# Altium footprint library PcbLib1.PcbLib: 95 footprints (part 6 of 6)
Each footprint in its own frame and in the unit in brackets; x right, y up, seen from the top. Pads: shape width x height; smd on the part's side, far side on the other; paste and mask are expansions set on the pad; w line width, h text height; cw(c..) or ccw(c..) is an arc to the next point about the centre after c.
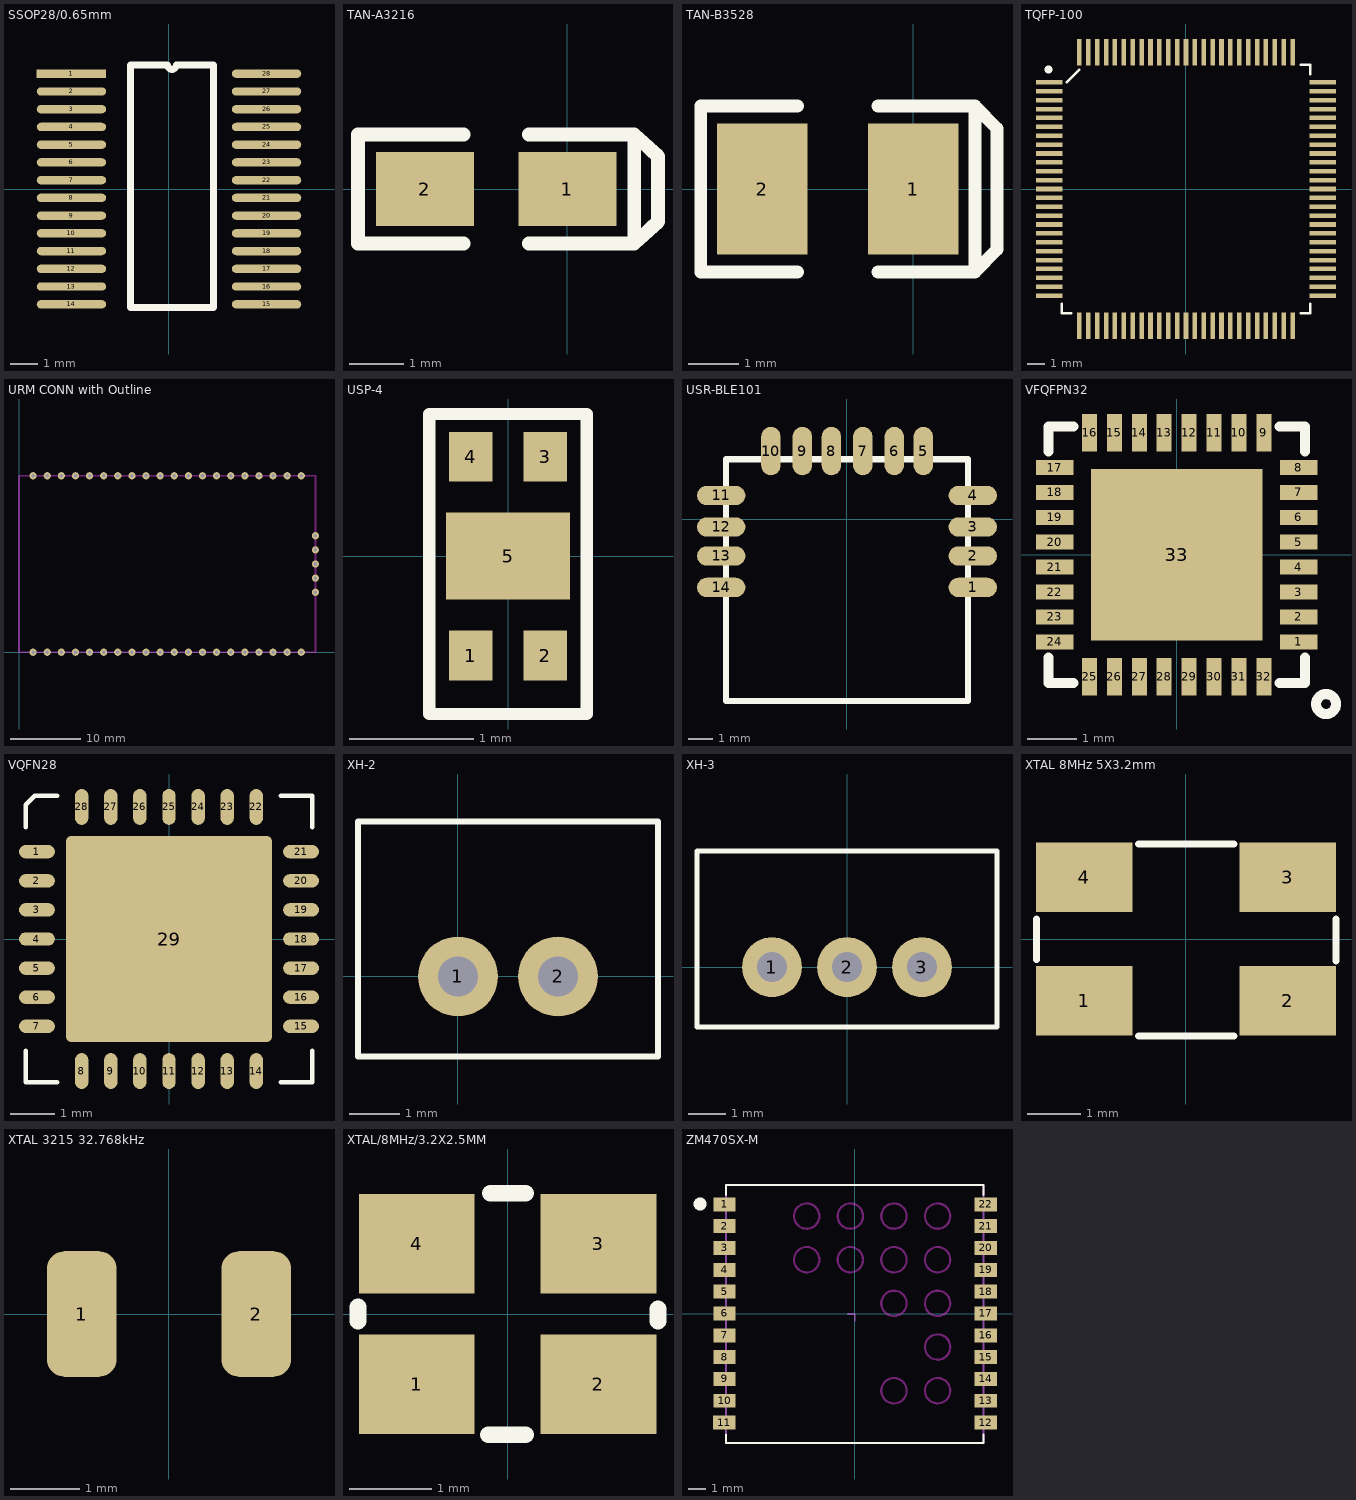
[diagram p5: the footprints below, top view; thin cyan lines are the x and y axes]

## SSOP28/0.65mm [mm]
pads (28):
  rect 2.54x0.305 smd: 1(-3.575,4.225)
  oval 2.54x0.305 smd: 2(-3.575,3.575) 3(-3.575,2.925) 4(-3.575,2.275) 5(-3.575,1.625) 6(-3.575,0.975) 7(-3.575,0.325) 8(-3.575,-0.325) 9(-3.575,-0.975) 10(-3.575,-1.625) 11(-3.575,-2.275) 12(-3.575,-2.925) 13(-3.575,-3.575) 14(-3.575,-4.225) 15(3.575,-4.225) 16(3.575,-3.575) 17(3.575,-2.925) 18(3.575,-2.275) 19(3.575,-1.625) 20(3.575,-0.975) 21(3.575,-0.325) 22(3.575,0.325) 23(3.575,0.975) 24(3.575,1.625) 25(3.575,2.275) 26(3.575,2.925) 27(3.575,3.575) 28(3.575,4.225)
Top Overlay:
  lines w0.254: -1.416,-4.348 -1.416,4.542 -0.051,4.542 ccw(c0.108,4.542) 0.267,4.542 1.632,4.542 1.632,-4.348 -1.416,-4.348
3D body: height 1.9, standoff 0, extent -3.812,-5.1 3.988,5.1

## TAN-A3216 [mm]
pads (2):
  rect 1.8x1.35 smd: 1(0,0) 2(-2.62,0)
Top Overlay:
  lines w0.254: -1.91,-1.002 -3.847,-1.002 -3.847,1.002 -1.91,1.002 ; -0.71,-1.002 1.227,-1.002 ; -0.71,1.002 1.227,1.002 ; 1.227,-1.002 1.663,-0.6 1.663,0.6 1.227,1.002 ; 1.227,-1.002 1.227,1.002
3D body: height 1.71, standoff 0, extent -3.01,-0.84 0.39,0.84

## TAN-B3528 [mm]
pads (2):
  rect 1.8x2.6 smd: 1(0,0) 2(-3,0)
Top Overlay:
  lines w0.254: -2.3,-1.65 -4.227,-1.65 -4.227,1.65 -2.3,1.65 ; -0.7,-1.65 1.227,-1.65 ; -0.7,1.65 1.227,1.65 ; 1.227,-1.65 1.227,1.65 ; 1.227,-1.65 1.663,-1.2 1.663,1.2 1.227,1.65
3D body: height 2.03, standoff 0, extent -3.35,-1.465 0.35,1.465

## TQFP-100 [mm]
pads (100):
  rect 1.5x0.254 smd: 1(-7.7,6) 2(-7.7,5.5) 3(-7.7,5) 4(-7.7,4.5) 5(-7.7,4) 6(-7.7,3.5) 7(-7.7,3) 8(-7.7,2.5) 9(-7.7,2) 10(-7.7,1.5) 11(-7.7,1) 12(-7.7,0.5) 13(-7.7,0) 14(-7.7,-0.5) 15(-7.7,-1) 16(-7.7,-1.5) 17(-7.7,-2) 18(-7.7,-2.5) 19(-7.7,-3) 20(-7.7,-3.5) 21(-7.7,-4) 22(-7.7,-4.5) 23(-7.7,-5) 24(-7.7,-5.5) 25(-7.7,-6) 51(7.7,-6) 52(7.7,-5.5) 53(7.7,-5) 54(7.7,-4.5) 55(7.7,-4) 56(7.7,-3.5) 57(7.7,-3) 58(7.7,-2.5) 59(7.7,-2) 60(7.7,-1.5) 61(7.7,-1) 62(7.7,-0.5) 63(7.7,0) 64(7.7,0.5) 65(7.7,1) 66(7.7,1.5) 67(7.7,2) 68(7.7,2.5) 69(7.7,3) 70(7.7,3.5) 71(7.7,4) 72(7.7,4.5) 73(7.7,5) 74(7.7,5.5) 75(7.7,6)
  rect 0.254x1.5 smd: 26(-6,-7.7) 27(-5.5,-7.7) 28(-5,-7.7) 29(-4.5,-7.7) 30(-4,-7.7) 31(-3.5,-7.7) 32(-3,-7.7) 33(-2.5,-7.7) 34(-2,-7.7) 35(-1.5,-7.7) 36(-1,-7.7) 37(-0.5,-7.7) 38(0,-7.7) 39(0.5,-7.7) 40(1,-7.7) 41(1.5,-7.7) 42(2,-7.7) 43(2.5,-7.7) 44(3,-7.7) 45(3.5,-7.7) 46(4,-7.7) 47(4.5,-7.7) 48(5,-7.7) 49(5.5,-7.7) 50(6,-7.7) 76(6,7.7) 77(5.5,7.7) 78(5,7.7) 79(4.5,7.7) 80(4,7.7) 81(3.5,7.7) 82(3,7.7) 83(2.5,7.7) 84(2,7.7) 85(1.5,7.7) 86(1,7.7) 87(0.5,7.7) 88(0,7.7) 89(-0.5,7.7) 90(-1,7.7) 91(-1.5,7.7) 92(-2,7.7) 93(-2.5,7.7) 94(-3,7.7) 95(-3.5,7.7) 96(-4,7.7) 97(-4.5,7.7) 98(-5,7.7) 99(-5.5,7.7) 100(-6,7.7)
Top Overlay:
  circle w0.254: c-7.747,6.731 r0.1
  lines w0.152: -7,-6.457 -7,-7 -6.457,-7 ; -6.712,6.018 -6.018,6.712 ; 6.457,-7 7,-7 7,-6.457 ; 6.457,7 7,7 7,6.457

## URM CONN with Outline [mil]
pads (45):
  round 40 hole 20 mask+2.5: 1(1574.8,983.13) 2(1496.06,983.13) 3(1417.32,983.13) 4(1338.58,983.13) 5(1259.84,983.13) 6(1181.1,983.13) 7(1102.36,983.13) 8(1023.62,983.13) 9(944.88,983.13) 10(866.14,983.13) 11(787.4,983.13) 12(708.66,983.13) 13(629.92,983.13) 14(551.18,983.13) 15(472.44,983.13) 16(393.7,983.13) 17(314.96,983.13) 18(236.22,983.13) 19(157.48,983.13) 20(78.74,983.13) 21(78.74,-1.13) 22(157.48,-1.13) 23(236.22,-1.13) 24(314.96,-1.13) 25(393.7,-1.13) 26(472.44,-1.13) 27(551.18,-1.13) 28(629.92,-1.13) 29(708.66,-1.13) 30(787.4,-1.13) 31(866.14,-1.13) 32(944.88,-1.13) 33(1023.62,-1.13) 34(1102.36,-1.13) 35(1181.1,-1.13) 36(1259.84,-1.13) 37(1338.58,-1.13) 38(1417.32,-1.13) 39(1496.06,-1.13) 40(1574.8,-1.13) G1(1653.54,648.48) G2(1653.54,491) G3(1653.54,333.52) NC(1653.54,412.26) TX(1653.54,569.74)
Keep-Out Layer:
  lines w10: 0,-1.13 1653.54,-1.13 1653.54,983.13 0,983.13 0,-1.13

## USP-4 [mm]
pads (5):
  rect 0.35x0.4 smd paste+0 mask+0.04: 1(-0.3,-0.8) 2(0.3,-0.8) 3(0.3,0.8) 4(-0.3,0.8)
  rect 1x0.7 smd paste+0 mask+0.04: 5(0,0)
Top Overlay:
  lines w0.1: -0.635,-1.27 -0.635,1.143 0.635,1.143 0.635,-1.27 -0.635,-1.27

## USR-BLE101 [mm]
pads (14):
  oval 2x0.8 smd: 1(5.2,-2.818) 2(5.2,-1.518) 3(5.2,-0.318) 4(5.2,0.982) 11(-5.2,0.982) 12(-5.2,-0.318) 13(-5.2,-1.518) 14(-5.2,-2.818)
  oval 0.8x2 smd: 5(3.154,2.818) 6(1.954,2.818) 7(0.654,2.818) 8(-0.646,2.818) 9(-1.846,2.818) 10(-3.146,2.818)
Top Overlay:
  lines w0.254: -5,-7.518 5,-7.518 5,2.482 -5,2.482 -5,-7.518

## VFQFPN32 [mm] "CR95HF"
pads (33):
  rect 0.75x0.3 smd paste+0 mask+0.04: 1(2.45,-1.75) 2(2.45,-1.25) 3(2.45,-0.75) 4(2.45,-0.25) 5(2.45,0.25) 6(2.45,0.75) 7(2.45,1.25) 8(2.45,1.75) 17(-2.45,1.75) 18(-2.45,1.25) 19(-2.45,0.75) 20(-2.45,0.25) 21(-2.45,-0.25) 22(-2.45,-0.75) 23(-2.45,-1.25) 24(-2.45,-1.75)
  rect 0.3x0.75 smd paste+0 mask+0.04: 9(1.75,2.45) 10(1.25,2.45) 11(0.75,2.45) 12(0.25,2.45) 13(-0.25,2.45) 14(-0.75,2.45) 15(-1.25,2.45) 16(-1.75,2.45) 25(-1.75,-2.45) 26(-1.25,-2.45) 27(-0.75,-2.45) 28(-0.25,-2.45) 29(0.25,-2.45) 30(0.75,-2.45) 31(1.25,-2.45) 32(1.75,-2.45)
  rect 3.45x3.45 smd paste-0.025 mask+0.1: 33(0,0)
Top Overlay:
  lines w0.2: -2.575,-2.069 -2.575,-2.575 -2.069,-2.575 ; -2.575,2.069 -2.575,2.575 -2.069,2.575 ; 2.069,-2.575 2.575,-2.575 2.575,-2.069 ; 2.069,2.575 2.575,2.575 2.575,2.069 ; 2.8,-3.007 2.801,-3.021 2.803,-3.035 2.806,-3.048 2.81,-3.062 2.815,-3.075 2.82,-3.088 2.827,-3.1 2.834,-3.112 2.842,-3.123 2.851,-3.134 2.861,-3.144 2.871,-3.153 2.882,-3.162 2.894,-3.17 2.906,-3.177 2.919,-3.183 2.932,-3.188 2.945,-3.192 2.958,-3.196 2.972,-3.198 2.986,-3.199 3,-3.2 3.014,-3.199 3.028,-3.198 3.042,-3.196 3.055,-3.192 3.068,-3.188 3.081,-3.183 3.094,-3.177 3.106,-3.17 3.118,-3.162 3.129,-3.153 3.139,-3.144 3.149,-3.134 3.158,-3.123 3.166,-3.112 3.173,-3.1 3.18,-3.088 3.185,-3.075 3.19,-3.062 3.194,-3.048 3.197,-3.035 3.199,-3.021 3.2,-3.007 3.2,-2.993 3.199,-2.979 3.197,-2.965 3.194,-2.952 3.19,-2.938 3.185,-2.925 3.18,-2.912 3.173,-2.9 3.166,-2.888 3.158,-2.877 3.149,-2.866 3.139,-2.856 3.129,-2.847 3.118,-2.838 3.106,-2.83 3.094,-2.823 3.081,-2.817 3.068,-2.812 3.055,-2.808 3.042,-2.804 3.028,-2.802 3.014,-2.8 3,-2.8 2.986,-2.8 2.972,-2.802 2.958,-2.804 2.945,-2.808 2.932,-2.812 2.919,-2.817 2.906,-2.823 2.894,-2.83 2.882,-2.838 2.871,-2.847 2.861,-2.856 2.851,-2.866 2.842,-2.877 2.834,-2.888 2.827,-2.9 2.82,-2.912 2.815,-2.925 2.81,-2.938 2.806,-2.952 2.803,-2.965 2.801,-2.979 2.8,-2.993 2.8,-3.007

## VQFN28 [mm]
pads (29):
  oval 0.8x0.3 smd mask+0.05: 1(-2.95,1.95) 2(-2.95,1.3) 3(-2.95,0.65) 4(-2.95,0) 5(-2.95,-0.65) 6(-2.95,-1.3) 7(-2.95,-1.95) 15(2.95,-1.95) 16(2.95,-1.3) 17(2.95,-0.65) 18(2.95,0) 19(2.95,0.65) 20(2.95,1.3) 21(2.95,1.95)
  oval 0.3x0.8 smd mask+0.05: 8(-1.95,-2.95) 9(-1.3,-2.95) 10(-0.65,-2.95) 11(0,-2.95) 12(0.65,-2.95) 13(1.3,-2.95) 14(1.95,-2.95) 22(1.95,2.95) 23(1.3,2.95) 24(0.65,2.95) 25(0,2.95) 26(-0.65,2.95) 27(-1.3,2.95) 28(-1.95,2.95)
  rrect5% 4.6x4.6 smd paste-3.3 mask+0.05: 29(0,0)
Top Overlay:
  lines w0.1: -3.2,-2.5 -3.2,-3.2 -2.5,-3.2 ; -3.2,2.5 -3.2,3 -3,3.2 -2.5,3.2 ; 2.5,-3.2 3.2,-3.2 3.2,-2.5 ; 2.5,3.2 3.2,3.2 3.2,2.5
Top Paste:
  region: -1.6,-0.8 -1.6,-1.6 -0.8,-1.6 -0.8,-0.8
  region: 0.8,-0.8 0.8,-1.6 1.6,-1.6 1.6,-0.8
  region: -0.4,-0.8 -0.4,-1.6 0.4,-1.6 0.4,-0.8
  region: 0.8,0.4 0.8,-0.4 1.6,-0.4 1.6,0.4
  region: -1.6,1.6 -1.6,0.8 -0.8,0.8 -0.8,1.6
  region: -0.4,1.6 -0.4,0.8 0.4,0.8 0.4,1.6
  region: -1.6,0.4 -1.6,-0.4 -0.8,-0.4 -0.8,0.4
  region: -0.4,0.4 -0.4,-0.4 0.4,-0.4 0.4,0.4
  region: 0.8,1.6 0.8,0.8 1.6,0.8 1.6,1.6

## XH-2 [mm]
pads (2):
  round 1.6 hole 0.8: 1(0,0) 2(2,0)
Top Overlay:
  lines w0.127: -2,-1.6 -2,0 -2,3.1 2,3.1 4,3.1 4,0 4,-1.6 -2,-1.6

## XH-3 [mm]
pads (3):
  round 1.6 hole 0.8: 1(-2,0) 2(0,0) 3(2,0)
Top Overlay:
  lines w0.127: -4,-1.6 0,-1.6 4,-1.6 4,0 4,3.1 0,3.1 -4,3.1 -4,0 -4,-1.6

## XTAL 8MHz 5X3.2mm [mm]
pads (4):
  rect 1.8x1.3 smd: 1(-1.9,-1.15) 2(1.9,-1.15) 3(1.9,1.15) 4(-1.9,1.15)
Top Overlay:
  lines w0.127: -2.789,-0.388 -2.789,0.374 ; -0.884,-1.81 0.894,-1.81 ; -0.884,1.771 0.894,1.771 ; 2.799,-0.413 2.799,0.374

## XTAL 3215 32.768kHz [mm]
pads (2):
  rrect50% 1x1.8 smd: 1(-1.25,0) 2(1.25,0)

## XTAL/8MHz/3.2X2.5MM [mm]
pads (4):
  rect 1.4x1.2 smd: 1(-1.1,-0.85) 2(1.1,-0.85) 3(1.1,0.85) 4(-1.1,0.85)
Top Overlay:
  lines w0.2: -1.811,-0.088 -1.811,0.09 ; -0.236,-1.46 0.221,-1.46 ; -0.211,1.461 0.221,1.461 ; 1.821,-0.088 1.821,0.064

## ZM470SX-M [mil]
pads (22):
  rect 51.18x32 smd paste-19.68: 1(-298.29,251.28) 2(-298.29,201.28) 3(-298.29,151.28) 4(-298.29,101.28) 5(-298.29,51.28) 6(-298.29,1.28) 7(-298.29,-48.72) 8(-298.29,-98.72) 9(-298.29,-148.72) 10(-298.29,-198.72) 12(300.28,-248.72) 13(300.28,-198.72) 14(300.28,-148.72) 15(300.28,-98.72) 16(300.28,-48.72) 17(300.28,1.28) 18(300.28,51.28) 19(300.28,101.28) 20(300.28,151.28) 21(300.28,201.28) 22(300.28,251.28)
  rect 52x32 smd paste-19.68: 11(-298.7,-248.72)
Top Layer keep-out:
  circle w5: c189.84,224.34 r29.05
  circle w5: c89.84,224.34 r29.05
  circle w5: c-10.16,224.34 r29.05
  circle w5: c-110.16,224.34 r29.05
  circle w5: c-110.16,124.34 r29.05
  circle w5: c-10.16,124.34 r29.05
  circle w5: c89.84,124.34 r29.05
  circle w5: c189.84,124.34 r29.05
  circle w5: c89.84,24.34 r29.05
  circle w5: c189.84,24.34 r29.05
  circle w5: c189.84,-75.66 r29.05
  circle w5: c89.84,-175.66 r29.05
  circle w5: c189.84,-175.66 r29.05
Top Overlay:
  circle w15.75: c-354.33,251.97 r7.09
  lines w5: -295.28,-295.28 295.28,-295.28 -295.27,-295.28 -295.27,-276.16 ; 295.27,-295.28 295.27,-276.16 ; 295.27,-295.27 295.28,-276.16 ; 295.27,295.27 -295.28,295.27 -295.28,273.34 -295.28,295.28 295.27,295.28 ; 295.27,295.28 295.27,273.34 295.27,295.28
Mechanical 15:
  lines w4.5: -15.75,0 0,0 0,-15.75
  lines w5: -295.28,-295.28 295.27,-295.28 ; -295.28,-295.28 -295.28,295.27 -295.28,295.28 ; -295.28,-295.28 295.27,-295.28 ; -295.28,295.28 295.27,295.28 ; -295.28,295.28 -294.28,295.28 ; -294.28,295.28 295.27,295.28 ; -294.28,295.28 -294.28,295.28 ; 295.27,-295.28 295.27,295.28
